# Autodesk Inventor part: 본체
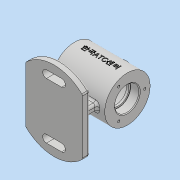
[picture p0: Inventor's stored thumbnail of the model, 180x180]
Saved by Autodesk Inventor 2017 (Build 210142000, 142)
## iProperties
Part Number: 본체
Material: 일반
Document SubType Name: Modeling
Designer: user
Density: 1 g/cm^3
Appearance: 기본값
Author: user
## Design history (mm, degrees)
sketch "스케치1"
  geometry: L1 (-35, 0)-(35, 0); L2 (-35, 0)-(-35, 30); L3 (-35, 30)-(35, 30); L4 (35, 30)-(35, 0); 2 further points
  constraints: 8 end point, 2 horizontal, 1 coincident, 1 midpoint, 1 perpendicular, 1 vertical
  dimensions: "d0" = 70 distance of L1.start L1.end; "d1" = 60 diameter of L3 L1
revolve "회전1" sketch "스케치1" stored, may be unused: angle "d2" = 90 deg
sketch "스케치2"
  geometry: L1 (-35, -30)-(-35, 30) reference; L2 (-35, 30)-(35, 30) reference; L3 (35, 30)-(35, -30) reference; L4 (35, -30)-(-35, -30) reference; L5 (-35, -30)-(-35, 30) reference; L6 (-35, 0)-(35, 0); L7 (-35, 0)-(-35, 16); L8 (-35, 16)-(-23.3, 16); L9 (-23, 15.7)-(-23, 14); L10 (-23, 14)-(-20, 14); L11 (-20, 14)-(-20, 22); L12 (-17, 25)-(17, 25); L13 (20, 22)-(20, 14); L14 (20, 14)-(23, 14); L15 (23, 14)-(23, 15.7); L16 (23.3, 16)-(35, 16); L17 (35, 0)-(35, 16); L18 (35, -30)-(35, 30) reference; A1 r 0.3 centre (-23.3, 15.7) between (-23, 15.7) and (-23.3, 16); A2 r 0.3 centre (23.3, 15.7) between (23.3, 16) and (23, 15.7); A3 r 3 centre (-17, 22) between (-17, 25) and (-20, 22); A4 r 3 centre (17, 22) between (20, 22) and (17, 25); 5 further points
  constraints: 24 end point, 13 point on line, 8 point on circle, 8 tangent, 6 perpendicular, 4 centre point, 2 equal radius, 2 midpoint, 1 collinear, 1 horizontal, 1 vertical
  dimensions: "d3" = 12 distance of L7.end point (-23, 16); "d4" = 32 diameter of L8 L6; "d6" = 28 diameter of L10 L6; "d7" = 40 distance of point (-20, 25) point (20, 25); "d8" = 50 diameter of L12 L6; "d9" = 12 distance of point (23, 16) L16.end; "d10" = 3 distance of L9.end L10.end; "d11" = 0.3 radius of A1; "d12" = 3 radius of A3
revolve "회전2" sketch "스케치2" stored, may be unused: angle "d13" = 90 deg
node "작업 평면1"
sketch "스케치3"
  geometry: L1 (-37.5, 98.299)-(37.5, 98.299); L2 (37.5, 98.299)-(37.5, -98.299); L3 (37.5, -98.299)-(-37.5, -98.299); L4 (-37.5, -98.299)-(-37.5, 98.299); L5 (-37.5, 98.299)-(37.5, -98.299); L6 (37.5, 98.299)-(-37.5, -98.299); L7 (37.5, -36.742)-(37.5, 36.742); L8 (-37.5, -36.742)-(-37.5, 36.742); A1 r 52.5 centre (0, 0) between (37.5, 36.742) and (-37.5, 36.742); A2 r 52.5 centre (0, 0) between (-37.5, -36.742) and (37.5, -36.742); 1 further point
  constraints: 16 end point, 4 point on circle, 4 point on line, 2 centre point, 2 midpoint, 2 parallel, 1 coincident, 1 collinear, 1 horizontal, 1 perpendicular, 1 vertical
  dimensions: "d16" = 75 distance of L2.end L3.end; "d17" = 52.5 radius of A2; "d18" = 52.5 radius of A1
extrude "돌출1" join sketch "스케치3" distance "d19" = 10; taper "d20" = 0 deg
sketch "스케치4"
  geometry: L1 (37.5, -36.742)-(37.5, 36.742) reference; L2 (-10, 37)-(10, 37); L3 (-10, 32)-(10, 32); L4 (10, 42)-(-10, 42); A1 r 52.5 centre (0, 0) between (37.5, 36.742) and (-37.5, 36.742) reference; A2 r 5 centre (-10, 37) between (-10, 42) and (-10, 32); A3 r 5 centre (10, 37) between (10, 32) and (10, 42); 1 further point
  constraints: 8 end point, 4 point on circle, 4 tangent, 2 centre point, 1 horizontal, 1 midpoint, 1 parallel
  dimensions: "d21" = 10 distance of point (0, 37) L2.end; "d22" = 10 diameter of A3; "d23" = 37 distance of point (0, 37) A1.centre; "d24" = 37.5 distance from line of point (0, 37) L1
extrude "돌출2" cut sketch "스케치4" stored distance "d25" = 10; taper "d26" = 0 deg
sketch "스케치5"
  geometry: L1 (-37.5, 36.742)-(-37.5, -36.742) reference; L2 (-25, 5)-(25, 5); L3 (25, 5)-(25, -5); L4 (25, -5)-(-25, -5); L5 (-25, -5)-(-25, 5); A1 r 52.5 centre (0, 0) between (37.5, 36.742) and (-37.5, 36.742) reference; 2 further points
  constraints: 8 end point, 2 midpoint, 2 parallel, 1 horizontal, 1 horizontal alignment, 1 perpendicular, 1 vertical alignment
  dimensions: "d27" = 50 distance of L3.end L4.end; "d28" = 10 distance of L2.end L3.end; "d29" = 12.5 distance between parallel lines of L5 L1 (derived)
extrude "돌출3" join sketch "스케치5" stored distance "d30" = 10; taper "d31" = 0 deg
node "작업 평면2"
sketch "스케치6"
  geometry: C1 r 10 at (0, 0); 1 further point
  constraints: 1 centre point, 1 coincident
  dimensions: "d33" = 20 diameter of C1
extrude "돌출4" join sketch "스케치6" stored distance "d34" = 10; taper "d35" = 0 deg
sketch "스케치7"
  geometry: C1 r 10 at (0, 0) reference; 1 further point
  constraints: 1 coincident
hole "구멍1" sketch "스케치7" at (0, 0) diameter "d36" = 10.917; stored, may be unused: countersink angle "d40" = 90 deg, drill point angle "d42" = 118 deg; dims "d37" = 24, "d38" = 4, "d39" = 2, "d41" = 29.1
sketch "스케치8" dims "d43" = 46
  geometry: C1 r 16 at (0, 0) reference; C2 r 30 at (0, 0) reference; 2 further points
  constraints: 2 vertical alignment, 1 coincident, 2 other
hole "구멍2" sketch "스케치8" at (0, 23) diameter "d44" = 3.242; stored, may be unused: countersink angle "d48" = 90 deg, drill point angle "d50" = 118 deg; dims "d45" = 8, "d46" = 4, "d47" = 2, "d49" = 10
fillet "모깎기1" dims "d54" = 3
fillet "모깎기2" dims "d55" = 3
fillet "모깎기3" dims "d56" = 3
fillet "모깎기4" dims "d57" = 3
chamfer "모따기1" distance "d58" = 1; stored, may be unused: second distance "d59" = 2, angle "d60" = 45 deg
fillet "모깎기5" dims "d61" = 3
node "작업 평면3"
sketch "스케치9"
  geometry: L1 (-35, -30)-(-35, 30) reference; L2 (-35, 30)-(35, 30) reference; 2 further points
  constraints: 1 other
  dimensions: "d63" = 35 distance from line of point (0, 0) L1; "d64" = 30 distance from line of point (0, 0) L2
feature "엠보싱1" sketch "스케치9" dims "d3" = 12, "d4" = 32, "d6" = 28, "d7" = 40, "d8" = 50, "d9" = 12, "d10" = 3, "d11" = 0.3, "d12" = 3, "d65" = 0.5, "d66" = 0
node "솔리드1"
mirror "미러1"
pattern_circular "원형 패턴1" dims angle "d52" = 360 deg
mirror "미러2"
node "절단 모서리 투영1"
other parameters: "d14" = -62, "d15" = 105, "d32" = 33
